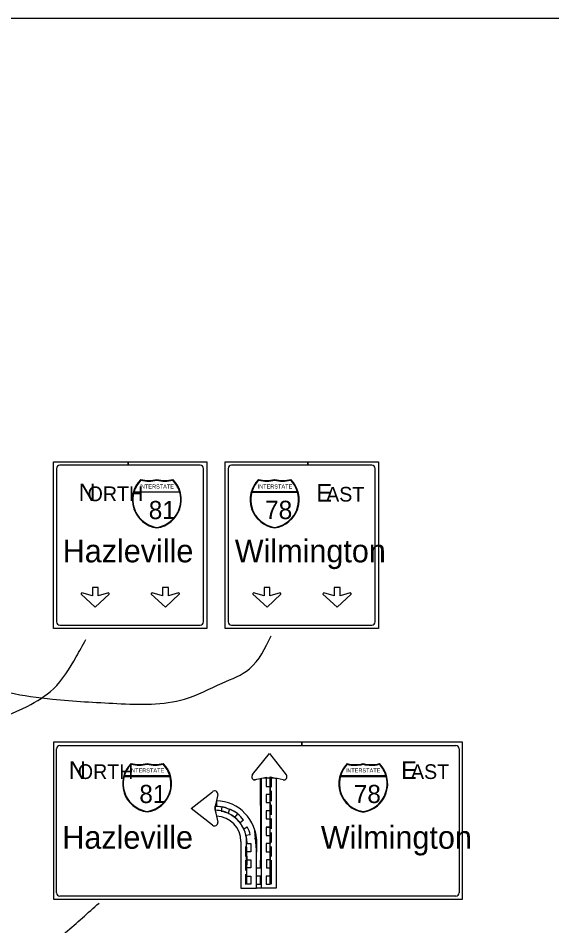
# Model space of a CAD drawing. Extents: x 640994 to 644422, y 298458 to 299646.
# Drawn here: x 642038.9 to 642202.5, y 298758.5 to 299036.6 of the extents above; entities that cross this region are included whole.
import ezdxf

# ---------------------------------------------------------------- set-up
doc = ezdxf.new("R2010")
doc.units = 0
doc.layers.add('1', color=7, linetype='Continuous')
doc.layers.add('2', color=7, linetype='Continuous')

msp = doc.modelspace()

# ---------------------------------------------------------------- linework, layer by layer
at = {"layer": '1'}
msp.add_line((641875.31, 299036.63), (642661.31, 299036.63), dxfattribs=at)
at = {"layer": '2'}
for p, q in [((642049.69, 298849.63), (642049.69, 298900.63)), ((642049.69, 298900.63), (642072.65, 298900.63)), ((642050.69, 298898.63), (642050.69, 298851.63)), ((642072.65, 298899.63), (642051.69, 298899.63)), ((642072.65, 298900.63), (642072.65, 298899.63)), ((642072.65, 298899.63), (642072.65, 298900.63)), ((642094.69, 298899.63), (642072.65, 298899.63)), ((642095.69, 298851.63), (642095.69, 298898.63)), ((642096.69, 298900.63), (642096.69, 298849.63)), ((642102.31, 298849.63), (642102.31, 298900.63)), ((642102.31, 298900.63), (642127.7, 298900.63)), ((642103.31, 298898.63), (642103.31, 298851.63)), ((642127.7, 298899.63), (642104.31, 298899.63)), ((642127.7, 298900.63), (642127.7, 298899.63)), ((642127.7, 298899.63), (642127.7, 298900.63)), ((642127.7, 298900.63), (642149.31, 298900.63)), ((642147.31, 298899.63), (642127.7, 298899.63)), ((642148.31, 298851.63), (642148.31, 298898.63)), ((642149.31, 298900.63), (642149.31, 298849.63)), ((642076.56, 298895), (642076.56, 298895)), ((642081.44, 298895), (642081.44, 298895)), ((642086.31, 298895), (642086.31, 298895)), ((642112.69, 298895), (642112.69, 298895)), ((642117.56, 298895), (642117.56, 298895)), ((642122.44, 298895), (642122.44, 298895)), ((642064.94, 298890.88), (642064.94, 298890.88)), ((642064.94, 298890.88), (642064.94, 298890.88)), ((642064.94, 298890.88), (642064.94, 298890.88)), ((642064.94, 298890.88), (642064.94, 298890.88)), ((642074.44, 298891.5), (642088.44, 298891.5)), ((642088.44, 298891.38), (642074.44, 298891.38)), ((642110.44, 298891.38), (642124.56, 298891.38)), ((642124.44, 298891.5), (642110.56, 298891.5)), ((642081.19, 298887.25), (642081.19, 298887.25)), ((642081.19, 298887.25), (642081.19, 298887.25)), ((642081.19, 298887.25), (642081.19, 298887.25)), ((642117.81, 298887.25), (642117.81, 298887.25)), ((642117.81, 298887.25), (642117.81, 298887.25)), ((642117.81, 298887.25), (642117.81, 298887.25)), ((642078.94, 298885), (642078.94, 298885)), ((642058.19, 298860.13), (642062.56, 298856.13)), ((642061.69, 298859.63), (642058.44, 298860.5)), ((642063.44, 298862.13), (642061.69, 298862.13)), ((642062.56, 298856.13), (642066.81, 298860.13)), ((642066.56, 298860.5), (642063.44, 298859.63)), ((642079.69, 298860.13), (642084.06, 298856.13)), ((642083.19, 298859.63), (642079.94, 298860.5)), ((642084.94, 298862.13), (642083.19, 298862.13)), ((642084.06, 298856.13), (642088.31, 298860.13)), ((642088.06, 298860.5), (642084.94, 298859.63)), ((642110.81, 298860.13), (642115.19, 298856.13)), ((642114.31, 298859.63), (642111.06, 298860.5)), ((642116.06, 298862.13), (642114.31, 298862.13)), ((642115.19, 298856.13), (642119.44, 298860.13)), ((642119.19, 298860.5), (642116.06, 298859.63)), ((642132.31, 298860.13), (642136.69, 298856.13)), ((642135.81, 298859.63), (642132.56, 298860.5)), ((642137.56, 298862.13), (642135.81, 298862.13)), ((642136.69, 298856.13), (642140.94, 298860.13)), ((642140.69, 298860.5), (642137.56, 298859.63)), ((642096.69, 298849.63), (642049.69, 298849.63)), ((642051.69, 298850.63), (642094.69, 298850.63)), ((642149.31, 298849.63), (642102.31, 298849.63)), ((642104.31, 298850.63), (642147.31, 298850.63)), ((642049.69, 298814.75), (642049.69, 298814.75)), ((642125.86, 298814.75), (642049.69, 298814.75)), ((642049.69, 298814.75), (642049.69, 298766.63)), ((642125.86, 298814.75), (642125.86, 298813.75)), ((642125.86, 298813.75), (642125.86, 298814.75)), ((642175.06, 298814.75), (642125.86, 298814.75)), ((642175.06, 298814.75), (642175.06, 298814.75)), ((642175.06, 298766.63), (642175.06, 298814.75)), ((642110.78, 298804.86), (642115.91, 298811.36)), ((642115.91, 298811.36), (642121.05, 298804.81)), ((642073.56, 298808), (642073.56, 298808)), ((642078.44, 298808), (642078.44, 298808)), ((642083.31, 298808), (642083.31, 298808)), ((642139.81, 298808), (642139.81, 298808)), ((642144.69, 298808), (642144.69, 298808)), ((642149.56, 298808), (642149.56, 298808)), ((642061.94, 298805.75), (642061.94, 298805.75)), ((642061.94, 298805.75), (642061.94, 298805.75)), ((642061.94, 298805.75), (642061.94, 298805.75)), ((642061.94, 298805.75), (642061.94, 298805.75)), ((642071.44, 298804.25), (642085.44, 298804.25)), ((642085.44, 298804.5), (642071.56, 298804.5)), ((642110.76, 298804.81), (642110.78, 298804.86)), ((642113.2, 298803.61), (642114.95, 298804.1)), ((642115.01, 298803.73), (642113.53, 298803.61)), ((642114.95, 298804.1), (642114.95, 298801.2)), ((642116.17, 298803.73), (642115.01, 298803.73)), ((642118.28, 298803.61), (642116.17, 298803.73)), ((642116.2, 298771.24), (642116.2, 298804.11)), ((642116.2, 298804.11), (642117.95, 298803.69)), ((642116.2, 298800.96), (642116.2, 298804.09)), ((642116.53, 298800.99), (642116.53, 298804.11)), ((642116.53, 298800.99), (642116.53, 298804.11)), ((642151.69, 298804.5), (642137.69, 298804.5)), ((642137.69, 298804.25), (642151.69, 298804.25)), ((642162.81, 298805.75), (642162.81, 298805.75)), ((642162.81, 298805.75), (642162.81, 298805.75)), ((642162.81, 298805.75), (642162.81, 298805.75)), ((642113.2, 298803.59), (642111.33, 298803.21)), ((642113.53, 298803.61), (642111.66, 298803.24)), ((642113.53, 298803.61), (642111.66, 298803.24)), ((642113.53, 298803.61), (642111.68, 298803.22)), ((642113.53, 298770.11), (642113.53, 298803.61)), ((642113.53, 298770.11), (642113.53, 298803.61)), ((642114.95, 298801.2), (642116.18, 298801.2)), ((642116.18, 298801.2), (642116.18, 298798.72)), ((642117.95, 298803.69), (642117.95, 298770.09)), ((642120.13, 298803.22), (642118.28, 298803.61)), ((642078.44, 298800.75), (642078.44, 298800.75)), ((642091.95, 298794.49), (642098.45, 298799.61)), ((642100.07, 298798.74), (642099.7, 298796.86)), ((642116.18, 298798.72), (642114.88, 298798.72)), ((642114.88, 298798.72), (642114.88, 298796.25)), ((642116.2, 298796.71), (642116.2, 298799.84)), ((642116.53, 298796.74), (642116.53, 298799.86)), ((642116.53, 298796.74), (642116.53, 298799.86)), ((642144.69, 298800.75), (642144.69, 298800.75)), ((642099.7, 298796.86), (642099.32, 298795.14)), ((642114.88, 298796.25), (642116.19, 298796.25)), ((642116.19, 298796.25), (642116.19, 298793.73)), ((642116.2, 298792.46), (642116.2, 298795.59)), ((642116.53, 298792.49), (642116.53, 298795.61)), ((642116.53, 298792.49), (642116.53, 298795.61)), ((642098.45, 298789.36), (642091.95, 298794.49)), ((642099.29, 298793.9), (642099.7, 298792.11)), ((642099.32, 298795.11), (642099.32, 298793.86)), ((642099.32, 298793.86), (642099.7, 298792.11)), ((642116.19, 298793.73), (642114.95, 298793.73)), ((642114.95, 298793.73), (642114.95, 298791.28)), ((642099.7, 298792.11), (642100.07, 298790.24)), ((642108.03, 298790.9), (642106.93, 298790.09)), ((642114.95, 298791.28), (642116.21, 298791.28)), ((642116.2, 298788.21), (642116.2, 298791.34)), ((642116.21, 298791.28), (642116.21, 298788.73)), ((642116.53, 298788.24), (642116.53, 298791.36)), ((642116.53, 298788.24), (642116.53, 298791.36)), ((642108.05, 298788.24), (642109.15, 298788.81)), ((642111.49, 298787.66), (642111.46, 298787.73)), ((642111.46, 298787.73), (642111.67, 298786.94)), ((642116.21, 298788.73), (642114.95, 298788.73)), ((642114.95, 298788.73), (642114.95, 298788.73)), ((642114.95, 298788.73), (642116.18, 298788.73)), ((642116.18, 298788.72), (642114.95, 298788.72)), ((642114.95, 298788.72), (642114.95, 298786.22)), ((642116.18, 298788.73), (642116.18, 298788.72)), ((642116.2, 298783.96), (642116.2, 298787.09)), ((642116.53, 298783.99), (642116.53, 298787.11)), ((642116.53, 298783.99), (642116.53, 298787.11)), ((642107.2, 298784.36), (642107.2, 298770.09)), ((642110.05, 298786.38), (642108.74, 298786.22)), ((642108.97, 298771.24), (642108.93, 298784.41)), ((642111.94, 298784.75), (642111.47, 298785.52)), ((642111.47, 298785.52), (642111.95, 298784.66)), ((642111.67, 298786.94), (642111.79, 298786.32)), ((642111.79, 298786.32), (642111.9, 298785.42)), ((642111.9, 298785.42), (642111.94, 298784.75)), ((642111.95, 298784.09), (642111.95, 298784.3)), ((642114.95, 298786.22), (642116.2, 298786.22)), ((642116.2, 298786.22), (642116.2, 298783.73)), ((642108.62, 298782.84), (642108.62, 298779.71)), ((642108.95, 298782.62), (642108.95, 298779.74)), ((642108.95, 298782.62), (642108.95, 298779.74)), ((642110.19, 298783.74), (642110.18, 298781.23)), ((642111.94, 298770.09), (642111.95, 298784.09)), ((642111.94, 298781.12), (642111.95, 298782.82)), ((642116.2, 298783.73), (642114.95, 298783.73)), ((642114.95, 298783.73), (642114.95, 298781.21)), ((642116.2, 298779.71), (642116.2, 298782.84)), ((642116.53, 298779.74), (642116.53, 298782.86)), ((642116.53, 298779.74), (642116.53, 298782.86)), ((642110.18, 298781.23), (642108.94, 298781.23)), ((642108.96, 298778.74), (642108.95, 298775.49)), ((642108.96, 298778.74), (642108.95, 298775.49)), ((642110.19, 298778.73), (642110.19, 298776.23)), ((642114.95, 298781.21), (642116.19, 298781.21)), ((642116.19, 298778.72), (642114.98, 298778.72)), ((642114.98, 298778.72), (642114.98, 298776.23)), ((642116.19, 298781.21), (642116.19, 298778.72)), ((642108.62, 298778.59), (642108.62, 298775.46)), ((642110.19, 298776.23), (642108.95, 298776.23)), ((642114.98, 298776.23), (642116.2, 298776.23)), ((642116.2, 298775.46), (642116.2, 298778.59)), ((642116.53, 298775.49), (642116.53, 298778.61)), ((642116.53, 298775.49), (642116.53, 298778.61)), ((642108.62, 298774.34), (642108.62, 298771.21)), ((642108.95, 298774.36), (642108.95, 298771.24)), ((642108.95, 298774.36), (642108.95, 298771.24)), ((642110.19, 298773.74), (642110.2, 298771.24)), ((642114.96, 298773.76), (642114.96, 298771.24)), ((642116.2, 298774.34), (642116.2, 298775.46)), ((642116.2, 298771.21), (642116.2, 298774.34)), ((642116.53, 298774.36), (642116.53, 298775.49)), ((642116.53, 298774.36), (642116.53, 298775.49)), ((642116.53, 298771.24), (642116.53, 298774.36)), ((642116.53, 298771.24), (642116.53, 298774.36)), ((642110.2, 298771.24), (642108.97, 298771.24)), ((642111.94, 298771.24), (642113.24, 298771.24)), ((642114.96, 298771.24), (642116.2, 298771.24)), ((642107.2, 298770.09), (642111.94, 298770.09)), ((642111.97, 298770.11), (642113.2, 298770.11)), ((642111.97, 298770.11), (642113.2, 298770.11)), ((642117.95, 298770.09), (642113.24, 298770.09)), ((642049.69, 298766.63), (642175.06, 298766.63))]:
    msp.add_line(p, q, dxfattribs=at)
for points in [[(642072.65, 298900.63), (642096.69, 298900.63)], [(642061.69, 298862.13), (642061.69, 298859.63)], [(642063.44, 298859.63), (642063.44, 298862.13)], [(642083.19, 298862.13), (642083.19, 298859.63)], [(642084.94, 298859.63), (642084.94, 298862.13)], [(642114.31, 298862.13), (642114.31, 298859.63)], [(642116.06, 298859.63), (642116.06, 298862.13)], [(642135.81, 298862.13), (642135.81, 298859.63)], [(642137.56, 298859.63), (642137.56, 298862.13)], [(642050.69, 298768.63), (642050.69, 298812.75)], [(642051.69, 298813.75), (642125.86, 298813.75)], [(642125.86, 298813.75), (642173.06, 298813.75)], [(642174.06, 298812.75), (642174.06, 298768.63)], [(642113.24, 298770.09), (642111.94, 298770.09), (642111.94, 298771.24), (642113.24, 298771.24), (642113.24, 298773.74), (642111.94, 298773.74), (642111.95, 298776.24), (642113.24, 298776.24), (642113.25, 298781.19), (642113.26, 298786.85), (642113.2, 298803.61)], [(642099.7, 298796.86), (642099.68, 298795.13), (642099.32, 298795.14)], [(642103.42, 298792.91), (642103.49, 298792.89), (642103.19, 298793.03), (642102.52, 298793.33), (642101.93, 298793.51), (642101.59, 298793.6), (642100.48, 298793.81), (642099.88, 298793.87), (642099.32, 298793.91), (642099.31, 298795.15), (642099.91, 298795.15), (642100.73, 298795.08), (642101.99, 298794.85), (642102.62, 298794.67), (642103.11, 298794.49), (642103.97, 298794.14), (642103.88, 298794.18)], [(642102.7, 298794.63), (642102.31, 298794.76), (642102.16, 298794.79), (642101.71, 298794.91), (642101.45, 298794.97), (642101.33, 298794.99), (642101.09, 298793.69), (642101.28, 298793.66), (642101.52, 298793.63), (642101.83, 298793.51), (642101.89, 298793.49), (642101.89, 298793.48), (642101.89, 298793.49), (642102.02, 298793.45), (642102.06, 298793.44), (642102.04, 298793.48), (642102.06, 298793.44), (642102.32, 298793.36)], [(642106.2, 298792.78), (642105.18, 298793.51), (642104.03, 298794.15), (642103.72, 298794.27), (642103.24, 298793.02), (642104.41, 298792.4), (642105.5, 298791.57), (642105.68, 298791.41), (642105.77, 298791.34), (642105.78, 298791.33)], [(642106.4, 298790.71), (642106.56, 298790.52), (642106.01, 298791.12), (642105.22, 298791.83), (642105.32, 298791.72), (642106.21, 298792.8), (642106.19, 298792.79), (642106.21, 298792.78), (642106.17, 298792.81)], [(642111.95, 298784.66), (642111.95, 298781.81), (642111.49, 298787.66)], [(642108.74, 298786.22), (642108.91, 298785.05), (642108.96, 298783.74), (642110.19, 298783.74)], [(642111.95, 298784.3), (642111.95, 298784.3), (642111.95, 298784.14)], [(642111.95, 298784.14), (642111.95, 298781.24), (642111.94, 298781.12)], [(642111.95, 298782.82), (642111.96, 298783.73), (642111.95, 298784.09)], [(642108.94, 298781.23), (642108.96, 298778.73), (642110.19, 298778.73)], [(642108.95, 298776.23), (642108.95, 298773.74), (642110.19, 298773.74)], [(642116.2, 298776.23), (642116.2, 298773.76), (642114.96, 298773.76)], [(642173.06, 298767.63), (642051.69, 298767.63)]]:
    msp.add_lwpolyline(points, dxfattribs=at)
for centre, radius, start, end in [((642051.69, 298898.63), 1, 90, 180), ((642094.69, 298898.63), 1, 0, 90), ((642104.31, 298898.63), 1, 90, 180), ((642147.31, 298898.63), 1, 0, 90), ((642082.65, 298889.06), 8.74, 135, 261.8699), ((642082.65, 298889.06), 8.56, 135.6924, 163.2072), ((642078.94, 298904.98), 10.04, 255.75, 284.25), ((642078.94, 298904.98), 10.23, 256.3405, 283.989), ((642080.18, 298889.06), 8.74, 278.1301, 45), ((642083.89, 298904.98), 10.04, 255.75, 284.25), ((642083.89, 298904.98), 10.23, 256.011, 283.6595), ((642080.18, 298889.06), 8.56, 16.7928, 44.3076), ((642118.77, 298889.06), 8.74, 135, 261.8699), ((642118.77, 298889.06), 8.56, 135.6924, 163.2072), ((642115.06, 298904.98), 10.04, 255.75, 284.25), ((642115.06, 298904.98), 10.23, 256.3405, 283.989), ((642120.01, 298904.98), 10.04, 255.75, 284.25), ((642116.3, 298889.06), 8.74, 278.1301, 45), ((642120.01, 298904.98), 10.23, 256.011, 283.6595), ((642116.3, 298889.06), 8.56, 16.7928, 44.3076), ((642082.65, 298889.06), 8.56, 164.4869, 261.8699), ((642080.18, 298889.06), 8.56, 278.1301, 15.5131), ((642118.77, 298889.06), 8.56, 164.4869, 261.8699), ((642116.3, 298889.06), 8.56, 278.1301, 15.5131), ((642058.41, 298860.27), 0.217, 75.9638, 226.9667), ((642066.63, 298860.27), 0.217, 313.0251, 104.0537), ((642079.91, 298860.27), 0.217, 75.9638, 226.9667), ((642088.13, 298860.27), 0.217, 313.0251, 104.0537), ((642111.04, 298860.27), 0.217, 75.9638, 226.9667), ((642119.25, 298860.27), 0.217, 313.0251, 104.0537), ((642132.54, 298860.27), 0.217, 75.9638, 226.9667), ((642140.75, 298860.27), 0.217, 313.0251, 104.0537), ((642051.69, 298851.63), 1, 180, 270), ((642094.69, 298851.63), 1, 270, 0), ((642104.31, 298851.63), 1, 180, 270), ((642147.31, 298851.63), 1, 270, 0), ((642051.69, 298812.75), 1, 90, 180), ((642173.06, 298812.75), 1, 0, 90), ((642079.68, 298802.05), 8.74, 135, 261.8699), ((642079.68, 298802.05), 8.56, 135.6924, 163.2072), ((642075.97, 298817.97), 10.04, 255.75, 284.25), ((642075.97, 298817.97), 10.23, 256.3405, 283.989), ((642080.91, 298817.97), 10.04, 255.75, 284.25), ((642077.2, 298802.05), 8.74, 278.1301, 45), ((642080.91, 298817.97), 10.23, 256.011, 283.6595), ((642077.2, 298802.05), 8.56, 16.7928, 44.3076), ((642145.92, 298802.02), 8.74, 135, 261.8699), ((642145.92, 298802.02), 8.56, 135.6924, 163.2072), ((642142.21, 298817.94), 10.04, 255.75, 284.25), ((642142.21, 298817.94), 10.23, 256.3405, 283.989), ((642147.16, 298817.94), 10.04, 255.75, 284.25), ((642143.45, 298802.02), 8.74, 278.1301, 45), ((642147.16, 298817.94), 10.23, 256.011, 283.6595), ((642143.45, 298802.02), 8.56, 16.7928, 44.3076), ((642079.68, 298802.05), 8.56, 164.4869, 261.8699), ((642077.2, 298802.05), 8.56, 278.1301, 15.5131), ((642111.5, 298804.18), 0.978, 139.8521, 280.5176), ((642120.31, 298804.18), 0.978, 259.4824, 40.1479), ((642145.92, 298802.02), 8.56, 164.4869, 261.8699), ((642143.45, 298802.02), 8.56, 278.1301, 15.5131), ((642099.13, 298798.89), 0.978, 349.4824, 130.1479), ((642099.31, 298784.22), 12.64, 359.3869, 88.2432), ((642099.21, 298784.18), 9.73, 1.3887, 89.5341), ((642099.45, 298784.36), 10.77, 72.4094, 90.6647), ((642099.23, 298784.14), 9.72, 64.4539, 71.4499), ((642100.06, 298785.25), 9.71, 50.798, 66.8365), ((642100.21, 298785.16), 9.7, 36.2782, 52.0652), ((642099.13, 298790.09), 0.978, 229.8521, 10.5176), ((642099.45, 298784.36), 7.75, 0, 88.1454), ((642100.35, 298785.3), 8.11, 41.8332, 48.0374), ((642095.11, 298781.64), 14.52, 26.999, 35.5695), ((642101.75, 298784.67), 8.48, 11.6278, 29.218), ((642051.69, 298768.63), 1, 180, 270), ((642173.06, 298768.63), 1, 270, 0)]:
    msp.add_arc(centre, radius, start, end, dxfattribs=at)
for points in [[(641987.31, 298846.25), (641987.94, 298841.75), (641989.44, 298837.38), (641993.44, 298831.75), (642002.31, 298826), (642013.69, 298822.38), (642028.69, 298821.38), (642041.69, 298825.75), (642049.69, 298831.13), (642056.69, 298840.88), (642059.69, 298846.25)], [(642013.56, 298846.25), (642017.19, 298839.38), (642024.94, 298833.75), (642036.06, 298830), (642049.44, 298828), (642069.19, 298826.63), (642089.94, 298828), (642101.44, 298832.88), (642109.81, 298837.25), (642116.44, 298847.38)], [(641995.94, 298762.88), (641998.23, 298754.26), (642010.49, 298739.55), (642027.72, 298740.15), (642041.21, 298747.03), (642053.43, 298756.45), (642063.69, 298765.5)]]:
    msp.add_spline(points, degree=3, dxfattribs=at)

# ---------------------------------------------------------------- texts
for s, height, p in [('N', 5.38, (642057.44, 298888.63)), ('ORTH', 4.5, (642060.19, 298888.63)), ('INTERSTATE', 1.236, (642076.06, 298892.5)), ('INTERSTATE', 1.236, (642112.31, 298892.5)), ('E', 5.38, (642130.31, 298888.5)), ('AST', 4.5, (642133.31, 298888.5)), ('81', 5.563, (642078.94, 298883.13)), ('78', 5.625, (642114.56, 298883.13)), ('Hazleville', 7, (642052.56, 298869.88)), ('Wilmington', 7, (642105.31, 298869.88)), ('N', 5.38, (642054.44, 298803.5)), ('ORTH', 4.5, (642057.19, 298803.5)), ('INTERSTATE', 1.236, (642073.06, 298805.5)), ('INTERSTATE', 1.236, (642139.31, 298805.5)), ('E', 5.38, (642156.31, 298803.5)), ('AST', 4.5, (642159.31, 298803.5)), ('81', 5.563, (642076.06, 298796.13)), ('78', 5.563, (642141.81, 298796.13)), ('Hazleville', 7, (642052.44, 298782.13)), ('Wilmington', 7, (642131.69, 298782.13))]:
    msp.add_text(s, height=height, dxfattribs=at).set_placement(p)

doc.saveas('drawing.dxf')
